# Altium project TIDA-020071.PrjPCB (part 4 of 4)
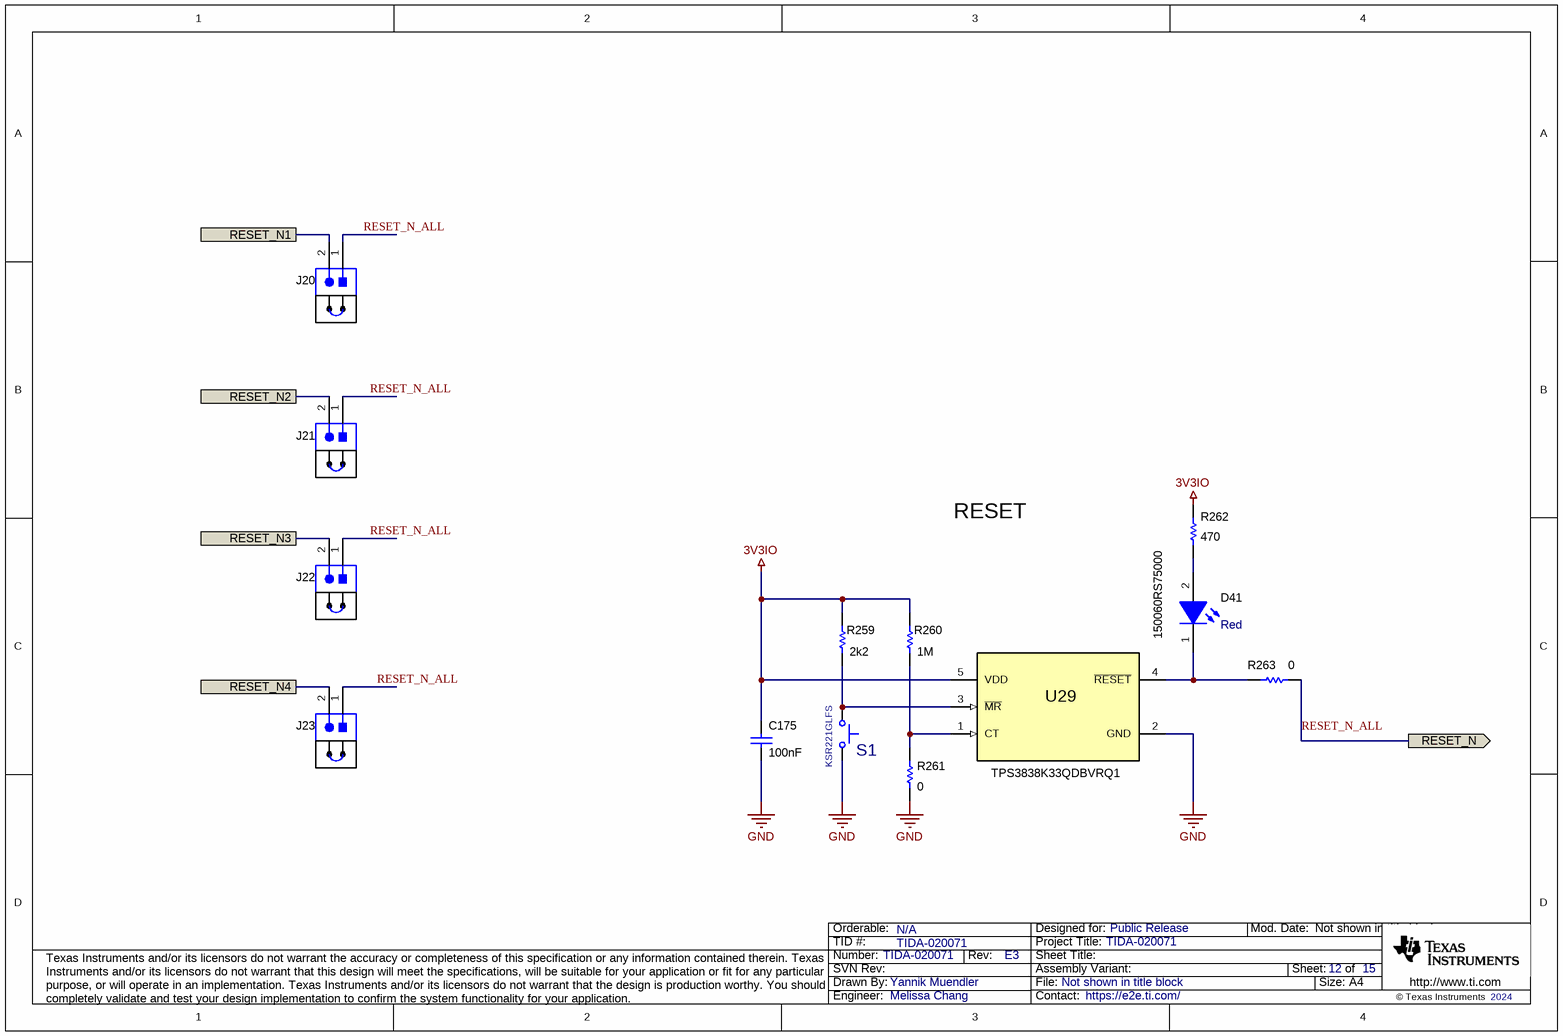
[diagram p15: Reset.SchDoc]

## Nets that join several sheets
3V3: Connector (7 pins), MDIO_MUX (6 pins)
3V3IO: CLOCK (5 pins), Connector (3V3IO.1 J1.100 J1.102 J1.104), Reset (5 pins)
5V0: 721-01 (7 pins), 721-02 (6 pins), 818-03 (6 pins), 818-04 (6 pins), Connector (5V0.1 J1.78 J1.80 J1.82), MDIO_MUX (8 pins), HSS and Memory (12 pins)
12V0: Connector (12V0.1 J2.2 J2.4 J2.6), HSS and Memory (5 pins)
GND: 721-01 (71 pins), 721-02 (69 pins), 818-03 (71 pins), 818-04 (70 pins), CLOCK (C177.2 C178.2 U31.4 Y5.2), AVB Headers (J12.5 J19.1 J19.13), Connector (52 pins), Conn-Rb-01 (10 pins), Conn-Rb-02 (10 pins), Conn-TE-01 (10 pins), Conn-TE-02 (10 pins), MDIO_MUX (12 pins), HSS and Memory (11 pins), Reset (C175.2 R261.1 S1.2 U29.2)
721/725 Enable/1: 721-01 (R314.2 U1.17), Connector (R354.1)
721/725 Enable/2: 721-02 (R317.2 U7.17), Connector (R362.2)
CLKOUT-1: 721-01 (R58.1 U1.16), AVB Headers (R333.1)
CLKOUT-3: 818-03 (5 pins), AVB Headers (R413.1)
CLKOUT-4: 818-04 (R217.1 U19.16), AVB Headers (R418.1)
EE-A0: Connector (J1.19), HSS and Memory (R264.1 U30.1)
EE-A1: Connector (J1.21), HSS and Memory (R265.1 U30.2)
EE-A2: Connector (J1.23), HSS and Memory (R266.1 U30.3)
EE-SCL: Connector (J2.65), HSS and Memory (U30.6)
EE-SDA: Connector (J2.63), HSS and Memory (U30.5)
EE-WP: Connector (J1.25), HSS and Memory (R267.1 U30.7)
GPIO5_3: 818-03 (U13.20), AVB Headers (R410.1)
GPIO5_4: 818-04 (U19.20), AVB Headers (R415.1)
GPIO_ICSSG_1/2: Connector (J2.30), MDIO_MUX (J70_1.1 R309.2)
GPIO_ICSSG_3/4: Connector (J2.32), MDIO_MUX (J73_1.1 R313.2)
INH-1: 721-01 (INH-1.1 R3.1 R46.2 R275.2), Connector (R285.2)
INH-2: 721-02 (INH-2.1 R9.1 R99.2 R276.2), Connector (R286.2)
INH-3: 818-03 (INH-3.1 R45.1 R152.2 R277.2), Connector (R287.2)
INH-4: 818-04 (INH-4.1 R62.1 R205.2 R278.2), Connector (R288.2)
INT_N1: 721-01 (INT-1.1 R49.1 U1.2), Connector (R5.2)
INT_N2: 721-02 (INT-2.1 R102.1 U7.2), Connector (R6.2)
INT_N3: 818-03 (INT-3.1 R155.1 U13.2), Connector (R7.2)
INT_N4: 818-04 (INT-4.1 R208.1 U19.2), Connector (R8.2)
LED_0-1: 721-01 (J15.2 U1.35), AVB Headers (R330.1)
LED_1-1: 721-01 (J16.2 U1.6), AVB Headers (R332.1)
MDC1/2: 721-01 (R50.2), 721-02 (R103.2), MDIO_MUX (J72.1)
MDC3/4: 818-03 (R156.2), 818-04 (R209.2), MDIO_MUX (J75.1)
MDC_CPSW: Connector (R300.2), MDIO_MUX (U41.4 U43.4)
MDC_ICSSG_1/2: Connector (R302.1), MDIO_MUX (U41.6)
MDC_ICSSG_3/4: Connector (R304.1), MDIO_MUX (U43.6)
MDIO1/2: 721-01 (R51.2), 721-02 (R104.2), MDIO_MUX (J71.1)
MDIO3/4: 818-03 (R157.2), 818-04 (R210.2), MDIO_MUX (J74.1)
MDIO_CPSW: Connector (R268.1 R301.2), MDIO_MUX (U40.4 U42.4)
MDIO_ICSSG_1/2: Connector (R303.1 R306.2), MDIO_MUX (U40.6)
MDIO_ICSSG_3/4: Connector (R305.1 R312.1), MDIO_MUX (U42.6)
P0-R1-RCLK: 818-03 (R158.2), Connector (J2.73)
P0-R1-RCTL: 818-03 (R159.2), Connector (J2.71)
P0-R1-RD0: 818-03 (R160.2), Connector (J2.69)
P0-R1-RD1: 818-03 (R161.2), Connector (J2.77)
P0-R1-RD2: 818-03 (R162.2), Connector (J2.75)
P0-R1-RD3: 818-03 (R163.2), Connector (J2.79)
P0-R2-RCLK: 818-04 (R211.2), Connector (J2.7)
P0-R2-RCTL: 818-04 (R212.2), Connector (J2.11)
P0-R2-RD0: 818-04 (R213.2), Connector (J2.13)
P0-R2-RD1: 818-04 (R214.2), Connector (J2.15)
P0-R2-RD2: 818-04 (R215.2), Connector (J2.17)
P0-R2-RD3: 818-04 (R216.2), Connector (J2.9)
P1-R1-RCLK: 721-01 (R52.2), Connector (J2.86)
P1-R1-RCTL: 721-01 (R53.2), Connector (J2.92)
P1-R1-RD0: 721-01 (R54.2), Connector (J2.84)
P1-R1-RD1: 721-01 (R55.2), Connector (J2.88)
P1-R1-RD2: 721-01 (R56.2), Connector (J2.94)
P1-R1-RD3: 721-01 (R57.2), Connector (J2.90)
P1-R2-RCLK: 721-02 (R105.2), Connector (J2.49)
P1-R2-RCTL: 721-02 (R106.2), Connector (J2.47)
P1-R2-RD0: 721-02 (R107.2), Connector (J2.39)
P1-R2-RD1: 721-02 (R108.2), Connector (J2.43)
P1-R2-RD2: 721-02 (R109.2), Connector (J2.41)
P1-R2-RD3: 721-02 (R110.2), Connector (J2.45)
Pin18_2: 721-02 (R374.1 R375.2 U7.18), Connector (R363.1)
Pin18_3: 818-03 (R279.2 R382.1 R383.2 U13.18), AVB Headers (R412.1)
Pin18_4: 818-04 (R281.2 R390.1 R391.2 U19.18), AVB Headers (R417.1)
Pin19_2: 721-02 (R372.1 R373.2 U7.19), Connector (R364.2)
Pin19_3: 818-03 (R380.1 R381.2 U13.19), AVB Headers (R411.1)
Pin19_4: 818-04 (R388.1 R389.2 U19.19), AVB Headers (R416.1)
Pin_18_1: 721-01 (R345.1 R346.2 U1.18), Connector (R355.1)
Pin_19_1: 721-01 (R343.1 R344.2 U1.19), Connector (R356.1)
PoDL_12V_Port_J7: Conn-Rb-01 (R168.2), HSS and Memory (C145.1 U10.25 U10.26)
PoDL_12V_Port_J8: Conn-Rb-02 (R183.2), HSS and Memory (C136.1 U10.27 U10.28)
PoDL_12V_Port_J9: Conn-TE-01 (R187.2), HSS and Memory (C146.1 U10.17 U10.18)
PoDL_12V_Port_J10: Conn-TE-02 (R204.2), HSS and Memory (C147.1 U10.15 U10.16)
RESET_N1: 721-01 (R47.2 R48.1), Reset (J20.2)
RESET_N2: 721-02 (R100.2 R101.1), Reset (J21.2)
RESET_N3: 818-03 (R153.2 R154.1), Reset (J22.2)
RESET_N4: 818-04 (R206.2 R207.1), Reset (J23.2)
RESET_N_ALL: Connector (R1.2), Reset (5 pins)
STRP-1: 721-01 (R37.1 R38.2 R361.1 U1.14), AVB Headers (R400.1)
STRP-3: 818-03 (R143.1 R144.2 U13.14), AVB Headers (R409.1)
STRP-4: 818-04 (R196.1 R197.2 U19.14), AVB Headers (R414.1)
TRD1_N: 721-01 (U1.13), Conn-Rb-01 (C137.2 R221.2)
TRD1_P: 721-01 (U1.12), Conn-Rb-01 (C138.1 R222.2)
TRD2_N: 721-02 (U7.13), Conn-Rb-02 (C148.2 R232.2)
TRD2_P: 721-02 (U7.12), Conn-Rb-02 (C149.1 R233.2)
TRD3_N: 818-03 (U13.13), Conn-TE-01 (C159.2 R243.2)
TRD3_P: 818-03 (U13.12), Conn-TE-01 (C160.1 R244.2)
TRD4_N: 818-04 (U19.13), Conn-TE-02 (C167.2 R251.2)
TRD4_P: 818-04 (U19.12), Conn-TE-02 (C168.2 R252.2)
TX_CLK-1: 721-01 (U1.28), Connector (RN1.14)
TX_CLK-2: 721-02 (U7.28), Connector (RN2.12)
TX_CLK-3: 818-03 (U13.28), Connector (RN3.15)
TX_CLK-4: 818-04 (U19.28), Connector (RN4.4)
TX_CTRL-1: 721-01 (U1.29), Connector (RN1.12)
TX_CTRL-2: 721-02 (U7.29), Connector (RN2.10)
TX_CTRL-3: 818-03 (U13.29), Connector (RN3.12)
TX_CTRL-4: 818-04 (U19.29), Connector (RN4.6)
TX_D0-1: 721-01 (U1.33), Connector (RN1.11)
TX_D0-2: 721-02 (U7.33), Connector (RN2.13)
TX_D0-3: 818-03 (U13.33), Connector (RN3.11)
TX_D0-4: 818-04 (U19.33), Connector (RN4.3)
TX_D1-1: 721-01 (U1.32), Connector (RN1.15)
TX_D1-2: 721-02 (U7.32), Connector (RN2.15)
TX_D1-3: 818-03 (U13.32), Connector (RN3.10)
TX_D1-4: 818-04 (U19.32), Connector (RN4.2)
TX_D2-1: 721-01 (U1.31), Connector (RN1.13)
TX_D2-2: 721-02 (U7.31), Connector (RN2.14)
TX_D2-3: 818-03 (U13.31), Connector (RN3.14)
TX_D2-4: 818-04 (U19.31), Connector (RN4.5)
TX_D3-1: 721-01 (U1.30), Connector (RN1.10)
TX_D3-2: 721-02 (U7.30), Connector (RN2.11)
TX_D3-3: 818-03 (U13.30), Connector (RN3.13)
TX_D3-4: 818-04 (U19.30), Connector (RN4.7)
WAKE_N: 721-01 (R347.2), 721-02 (R376.2), 818-03 (R384.2), 818-04 (R392.2), Connector (R2.2)
Y0: 721-01 (R271.2), CLOCK (U31.3)
Y1: 721-02 (R272.2), CLOCK (U31.8)
Y2: 818-03 (R273.2), CLOCK (U31.5)
Y3: 818-04 (R274.2), CLOCK (U31.7)

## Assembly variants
001: not fitted C1 C14 C31 C34 C35 C48 C65 C68 C69 C75 C78 C80 C81 C82 C83 C87 C88 C89 C99 C102 C109 C112 C114 C115 C116 C117 C121 C122 C123 C133 C137 C138 C139 C140 C148 C149 C150 C151 C159 C160 C161 C162 C167 C168 C169 C170 C178 C320 C322 D33 D34 D35 D36 D37 D38 D39 D40 FID1 FID2 FID3 L17 L18 L25 L26 L27 L28 R2 R4 R10 R24 R30 R32 R34 R35 R36 R37 R38 R61 R63 R77 R81 R83 R85 R87 R89 R90 R91 R98 R115 R116 R130 R134 R136 R138 R140 R142 R143 R144 R167 R168 R169 R183 R187 R189 R191 R193 R194 R195 R197 R204 R223 R224 R229 R234 R235 R245 R246 R253 R254 R259 R260 R267 R268 R271 R272 R273 R274 R279 R280 R281 R282 R285 R286 R287 R288 R320 R321 R322 R323 R324 R332 R333 R340 R341 R342 R343 R344 R345 R346 R348 R350 R353 R354 R355 R356 R361 R362 R363 R364 R370 R371 R372 R373 R374 R375 R378 R379 R381 R382 R383 R386 R387 R389 R390 R391 R410 R415 U25 U26 U27 U28 Y5 Y6 Y7 Y8 Y9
